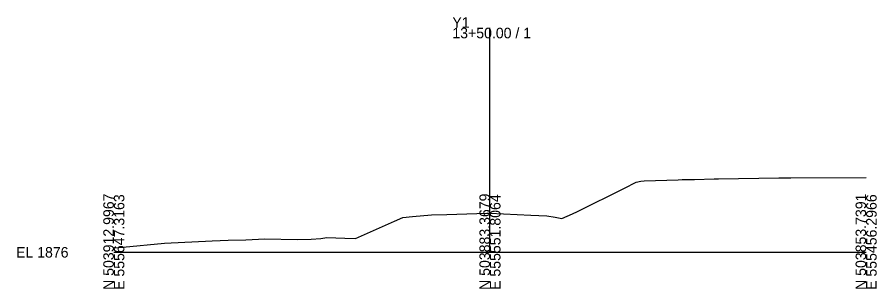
# Model space of a CAD drawing. Extents: x -26 to 203, y -10 to 5015.
# Drawn here: x -25.7 to 202.8, y 3490.3 to 3562.4 of the extents above; entities that cross this region are included whole.
import ezdxf

# ---------------------------------------------------------------- set-up
doc = ezdxf.new("R2010")
doc.units = 0
doc.layers.add('Exist Cross Section Cell', color=7, linetype='Continuous')
doc.layers.add('Exist XS Ground Line', color=7, linetype='Continuous')

msp = doc.modelspace()

# ---------------------------------------------------------------- linework, layer by layer
at = {"layer": 'Exist Cross Section Cell'}
for p, q in [((100, 3500), (100, 3559.64)), ((0, 3500), (100, 3500)), ((100, 3500), (200, 3500))]:
    msp.add_line(p, q, dxfattribs=at)
at = {"layer": 'Exist XS Ground Line'}
for p, q in [((154.38, 3519.35), (159.61, 3519.54)), ((159.61, 3519.54), (160.71, 3519.54)), ((160.71, 3519.54), (176.8, 3519.75)), ((176.8, 3519.75), (179.96, 3519.77)), ((179.96, 3519.77), (200, 3519.88)), ((135.77, 3517.07), (138.89, 3518.65)), ((138.89, 3518.65), (140.1, 3518.87)), ((140.1, 3518.87), (140.98, 3519)), ((140.98, 3519), (149.99, 3519.27)), ((149.99, 3519.27), (151.13, 3519.3)), ((151.13, 3519.3), (154.38, 3519.35)), ((123.31, 3510.8), (135.77, 3517.07)), ((88.51, 3510.06), (99.2, 3510.41)), ((99.2, 3510.41), (100, 3510.37)), ((100, 3510.37), (110.83, 3509.86)), ((121.96, 3510.24), (123.31, 3510.8)), ((64.25, 3503.69), (74.59, 3508.27)), ((74.59, 3508.27), (76.83, 3509.26)), ((76.83, 3509.26), (79.36, 3509.47)), ((79.36, 3509.47), (84.42, 3509.93)), ((84.42, 3509.93), (88.51, 3510.06)), ((110.83, 3509.86), (115.15, 3509.72)), ((115.15, 3509.72), (117.35, 3509.32)), ((117.35, 3509.32), (119.13, 3508.98)), ((119.13, 3508.98), (121.96, 3510.24)), ((35.06, 3503.33), (40.12, 3503.54)), ((40.12, 3503.54), (48.7, 3503.4)), ((48.7, 3503.4), (52.45, 3503.45)), ((52.45, 3503.45), (55.05, 3503.69)), ((55.05, 3503.69), (56.63, 3503.91)), ((56.63, 3503.91), (61.37, 3503.74)), ((61.37, 3503.74), (64.25, 3503.69)), ((0, 3501.23), (2.35, 3501.34)), ((2.35, 3501.34), (13.46, 3502.42)), ((13.46, 3502.42), (26.13, 3503.05)), ((26.13, 3503.05), (30.41, 3503.25)), ((30.41, 3503.25), (35.06, 3503.33))]:
    msp.add_line(p, q, dxfattribs=at)

# ---------------------------------------------------------------- texts
at = {"layer": 'Exist Cross Section Cell'}
for s, p in [('Y1', (90, 3559.64)), ('13+50.00 / 1', (90, 3556.84)), ('EL 1876', (-26, 3498.6))]:
    msp.add_text(s, height=2.8, dxfattribs=at).set_placement(p)
for s, p in [('N 503912.9967', (0, 3490)), ('E 555647.3163', (2.8, 3490)), ('N 503883.3679', (100, 3490)), ('E 555551.8064', (102.8, 3490)), ('N 503853.7391', (200, 3490)), ('E 555456.2966', (202.8, 3490))]:
    msp.add_text(s, height=2.8, rotation=90, dxfattribs=at).set_placement(p)

doc.saveas('drawing.dxf')
